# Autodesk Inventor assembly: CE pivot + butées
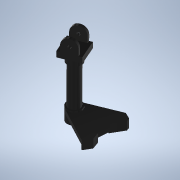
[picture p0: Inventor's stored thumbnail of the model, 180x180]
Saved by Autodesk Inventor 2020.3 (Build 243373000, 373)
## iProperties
Created: 2020-09
Part Number: CE pivot + butées
Document SubType Name: Assembly
Designer: ficho
Author: ficho
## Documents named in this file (3)
- G:\travail\année 2020-2021\2I2D\platine disque\platine 3D\CE pivot + butées.iam
- G:\travail\année 2020-2021\2I2D\platine disque\platine 3D\pivot bras.ipt
- G:\travail\année 2020-2021\2I2D\platine disque\platine 3D\butées bras.ipt
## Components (2 placed, 2 different names)
1. pivot bras:1 — Placage:2, Placage:3, Placage:4
2. butées bras:1 — Placage:2, Placage:3, Placage:4
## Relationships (3: Mate 3)
- Placage:2 [Mate]: pivot bras:1 ↔ butées bras:1
- Placage:3 [Mate]: pivot bras:1 ↔ butées bras:1
- Placage:4 [Mate]: pivot bras:1 ↔ butées bras:1
